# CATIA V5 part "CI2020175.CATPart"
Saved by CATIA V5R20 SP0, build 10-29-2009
Part number: CI2020175
Bounding box of the stored display mesh (mm): x -19 to 19, y -14.509 to 205, z -26.066 to 21.271
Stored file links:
  C:\Users\Raffaele\Desktop\3D X SITO CF\BOLEX\19-INCLINED ASSEMBLY REF_CI\CI2020175.CATPart

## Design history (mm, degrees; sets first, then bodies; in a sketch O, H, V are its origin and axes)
Set1
  DatumSurface1 to DatumSurface16 "MANIFOLD_SOLID_BREP #389"
  DatumSurface17 to DatumSurface39 "MANIFOLD_SOLID_BREP #1118"
Body1 (main body)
